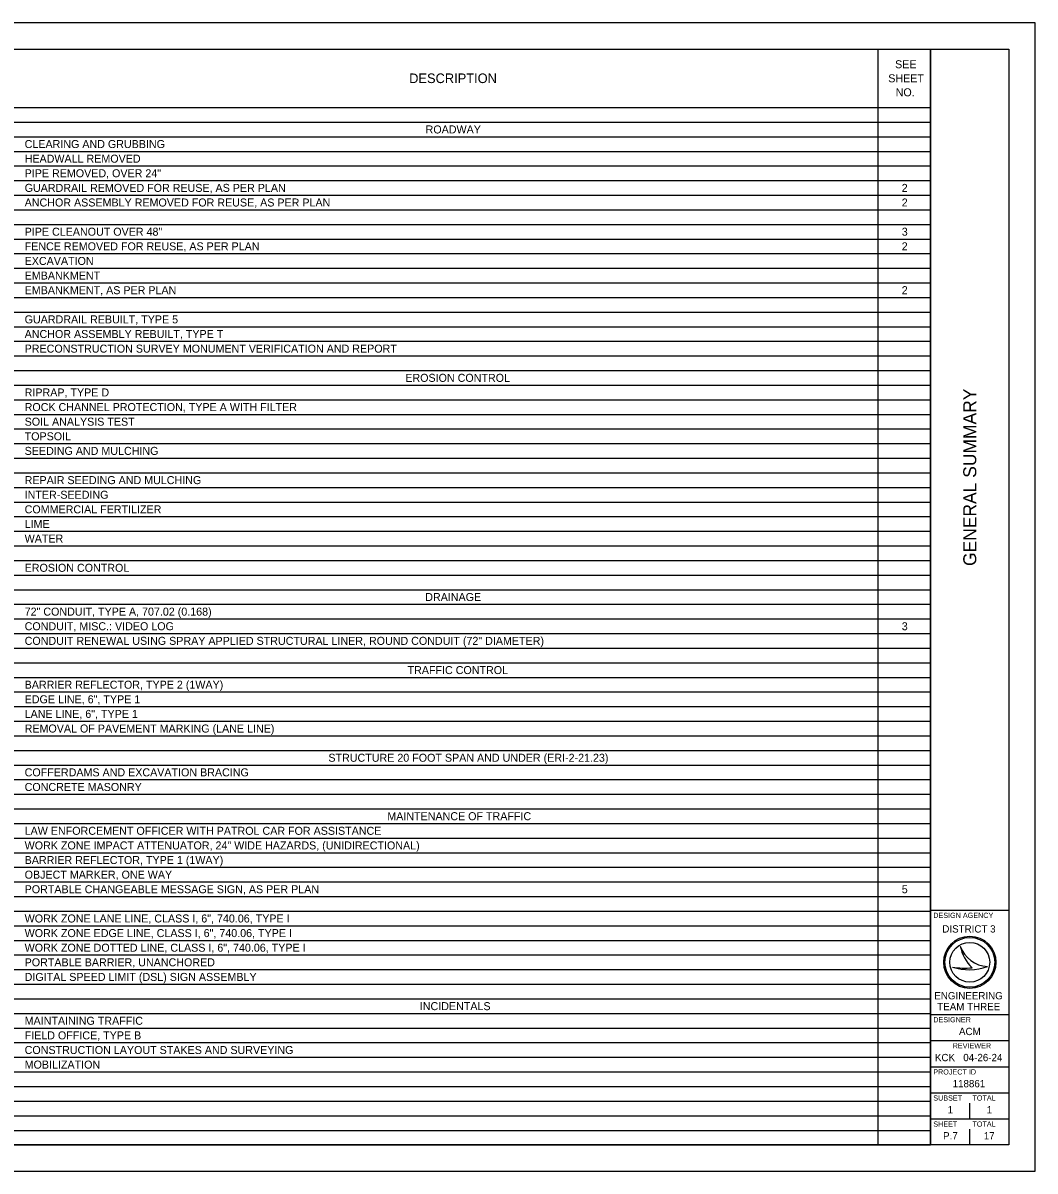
# Model space of a CAD drawing. Extents: x 0 to 34, y 0 to 22.
# Drawn here: x 14.61 to 34, y 0 to 22 of the extents above; entities that cross this region are included whole.
import ezdxf

# ---------------------------------------------------------------- set-up
doc = ezdxf.new("R2010")
doc.units = 0
for name, color, linetype in [('SH_Border', 7, 'Continuous'), ('SH_Cut_Line', 7, 'Continuous'), ('SH_Data', 7, 'Continuous'), ('SH_Text', 7, 'Continuous')]:
    doc.layers.add(name, color=color, linetype=linetype)

msp = doc.modelspace()

# ---------------------------------------------------------------- linework, layer by layer
at = {"layer": 'SH_Border'}
for p, q in [((32, 0.5), (32, 21.5)), ((32, 5), (33.5, 5)), ((32, 3), (33.5, 3)), ((32, 2.5), (33.5, 2.5)), ((32, 2), (33.5, 2)), ((32, 1.5), (33.5, 1.5)), ((32, 1), (33.5, 1))]:
    msp.add_line(p, q, dxfattribs=at)
msp.add_lwpolyline([(1.5, 21.5), (33.5, 21.5), (33.5, 0.5), (1.5, 0.5)], close=True, dxfattribs=at)
at = {"layer": 'SH_Cut_Line'}
msp.add_lwpolyline([(0, 0), (34, 0), (34, 22), (0, 22)], close=True, dxfattribs=at)
at = {"layer": 'SH_Data'}
for p, q in [((32.567, 4.31), (32.567, 4.31)), ((32.75, 4), (32.75, 4)), ((32.417, 3.91), (32.417, 3.91)), ((33.087, 3.919), (33.087, 3.919)), ((32.75, 1), (32.75, 1.3)), ((32.375, 0.675), (32.375, 0.675)), ((32.75, 0.5), (32.75, 0.8))]:
    msp.add_line(p, q, dxfattribs=at)
for radius in [0.5, 0.477, 0.477, 0.382]:
    msp.add_circle((32.75, 4), radius, dxfattribs=at)
for centre, radius, start, end in [((33.116, 4.498), 0.58, 198.9257, 198.9319), ((33.347, 4.47), 0.796, 191.6379, 191.6421), ((33.116, 4.498), 0.58, 198.9319, 267.1657), ((33.347, 4.47), 0.796, 191.6421, 226.0947), ((32.739, 4.87), 1.013, 251.4576, 290.0832), ((32.648, 5.154), 1.266, 259.4964, 259.4995), ((32.739, 4.87), 1.013, 251.4527, 251.4576), ((32.648, 5.154), 1.266, 259.4995, 276.6672)]:
    msp.add_arc(centre, radius, start, end, dxfattribs=at)
at = {"layer": 'SH_Text'}
for p, q in [((13.332, 21.5), (30.988, 21.5)), ((30.988, 21.5), (32, 21.5)), ((30.988, 21.5), (30.988, 21.22)), ((32, 21.5), (32, 21.22)), ((30.988, 21.22), (30.988, 20.94)), ((32, 21.22), (32, 20.94)), ((30.988, 20.94), (30.988, 20.66)), ((32, 20.94), (32, 20.66)), ((30.988, 20.66), (30.988, 20.38)), ((32, 20.66), (32, 20.38)), ((13.332, 20.38), (30.988, 20.38)), ((30.988, 20.38), (32, 20.38)), ((30.988, 20.38), (30.988, 20.1)), ((32, 20.38), (32, 20.1)), ((13.332, 20.1), (30.988, 20.1)), ((30.988, 20.1), (32, 20.1)), ((30.988, 20.1), (30.988, 18.7)), ((32, 20.1), (32, 18.7)), ((13.332, 19.82), (30.988, 19.82)), ((30.988, 19.82), (32, 19.82)), ((13.332, 19.54), (30.988, 19.54)), ((30.988, 19.54), (32, 19.54)), ((13.332, 19.26), (30.988, 19.26)), ((30.988, 19.26), (32, 19.26)), ((13.332, 18.98), (30.988, 18.98)), ((30.988, 18.98), (32, 18.98)), ((13.332, 18.7), (30.988, 18.7)), ((30.988, 18.7), (32, 18.7)), ((30.988, 18.7), (30.988, 18.14)), ((32, 18.7), (32, 18.14)), ((13.332, 18.42), (30.988, 18.42)), ((30.988, 18.42), (32, 18.42)), ((13.332, 18.14), (30.988, 18.14)), ((30.988, 18.14), (32, 18.14)), ((30.988, 18.14), (30.988, 17.86)), ((32, 18.14), (32, 17.86)), ((13.332, 17.86), (30.988, 17.86)), ((30.988, 17.86), (32, 17.86)), ((30.988, 17.86), (30.988, 17.58)), ((32, 17.86), (32, 17.58)), ((13.332, 17.58), (30.988, 17.58)), ((30.988, 17.58), (32, 17.58)), ((30.988, 17.58), (30.988, 17.3)), ((32, 17.58), (32, 17.3)), ((13.332, 17.3), (30.988, 17.3)), ((30.988, 17.3), (32, 17.3)), ((30.988, 17.3), (30.988, 17.02)), ((32, 17.3), (32, 17.02)), ((13.332, 17.02), (30.988, 17.02)), ((30.988, 17.02), (32, 17.02)), ((30.988, 17.02), (30.988, 16.74)), ((32, 17.02), (32, 16.74)), ((13.332, 16.74), (30.988, 16.74)), ((30.988, 16.74), (32, 16.74)), ((30.988, 16.74), (30.988, 16.18)), ((32, 16.74), (32, 16.18)), ((13.332, 16.46), (30.988, 16.46)), ((30.988, 16.46), (32, 16.46)), ((13.332, 16.18), (30.988, 16.18)), ((30.988, 16.18), (32, 16.18)), ((30.988, 16.18), (30.988, 15.9)), ((32, 16.18), (32, 15.9)), ((13.332, 15.9), (30.988, 15.9)), ((30.988, 15.9), (32, 15.9)), ((30.988, 15.9), (30.988, 15.62)), ((32, 15.9), (32, 15.62)), ((13.332, 15.62), (30.988, 15.62)), ((30.988, 15.62), (32, 15.62)), ((30.988, 15.62), (30.988, 15.34)), ((32, 15.62), (32, 15.34)), ((13.332, 15.34), (30.988, 15.34)), ((30.988, 15.34), (32, 15.34)), ((30.988, 15.34), (30.988, 14.78)), ((32, 15.34), (32, 14.78)), ((13.332, 15.06), (30.988, 15.06)), ((30.988, 15.06), (32, 15.06)), ((13.332, 14.78), (30.988, 14.78)), ((30.988, 14.78), (32, 14.78)), ((30.988, 14.78), (30.988, 14.5)), ((32, 14.78), (32, 14.5)), ((13.332, 14.5), (30.988, 14.5)), ((30.988, 14.5), (32, 14.5)), ((30.988, 14.5), (30.988, 14.22)), ((32, 14.5), (32, 14.22)), ((13.332, 14.22), (30.988, 14.22)), ((30.988, 14.22), (32, 14.22)), ((30.988, 14.22), (30.988, 13.94)), ((32, 14.22), (32, 13.94)), ((13.332, 13.94), (30.988, 13.94)), ((30.988, 13.94), (32, 13.94)), ((30.988, 13.94), (30.988, 11.7)), ((32, 13.94), (32, 11.7)), ((13.332, 13.66), (30.988, 13.66)), ((30.988, 13.66), (32, 13.66)), ((13.332, 13.38), (30.988, 13.38)), ((30.988, 13.38), (32, 13.38)), ((13.332, 13.1), (30.988, 13.1)), ((30.988, 13.1), (32, 13.1)), ((13.332, 12.82), (30.988, 12.82)), ((30.988, 12.82), (32, 12.82)), ((13.332, 12.54), (30.988, 12.54)), ((30.988, 12.54), (32, 12.54)), ((13.332, 12.26), (30.988, 12.26)), ((30.988, 12.26), (32, 12.26)), ((13.332, 11.98), (30.988, 11.98)), ((30.988, 11.98), (32, 11.98)), ((13.332, 11.7), (30.988, 11.7)), ((30.988, 11.7), (32, 11.7)), ((30.988, 11.7), (30.988, 11.42)), ((32, 11.7), (32, 11.42)), ((13.332, 11.42), (30.988, 11.42)), ((30.988, 11.42), (32, 11.42)), ((30.988, 11.42), (30.988, 10.3)), ((32, 11.42), (32, 10.3)), ((13.332, 11.14), (30.988, 11.14)), ((30.988, 11.14), (32, 11.14)), ((13.332, 10.86), (30.988, 10.86)), ((30.988, 10.86), (32, 10.86)), ((13.332, 10.58), (30.988, 10.58)), ((30.988, 10.58), (32, 10.58)), ((13.332, 10.3), (30.988, 10.3)), ((30.988, 10.3), (32, 10.3)), ((30.988, 10.3), (30.988, 10.02)), ((32, 10.3), (32, 10.02)), ((13.332, 10.02), (30.988, 10.02)), ((30.988, 10.02), (32, 10.02)), ((30.988, 10.02), (30.988, 9.74)), ((32, 10.02), (32, 9.74)), ((13.332, 9.74), (30.988, 9.74)), ((30.988, 9.74), (32, 9.74)), ((30.988, 9.74), (30.988, 8.9)), ((32, 9.74), (32, 8.9)), ((13.332, 9.46), (30.988, 9.46)), ((30.988, 9.46), (32, 9.46)), ((13.332, 9.18), (30.988, 9.18)), ((30.988, 9.18), (32, 9.18)), ((13.332, 8.9), (30.988, 8.9)), ((30.988, 8.9), (32, 8.9)), ((30.988, 8.9), (30.988, 8.34)), ((32, 8.9), (32, 8.34)), ((13.332, 8.62), (30.988, 8.62)), ((30.988, 8.62), (32, 8.62)), ((13.332, 8.34), (30.988, 8.34)), ((30.988, 8.34), (32, 8.34)), ((30.988, 8.34), (30.988, 7.5)), ((32, 8.34), (32, 7.5)), ((13.332, 8.06), (30.988, 8.06)), ((30.988, 8.06), (32, 8.06)), ((13.332, 7.78), (30.988, 7.78)), ((30.988, 7.78), (32, 7.78)), ((13.332, 7.5), (30.988, 7.5)), ((30.988, 7.5), (32, 7.5)), ((30.988, 7.5), (30.988, 6.94)), ((32, 7.5), (32, 6.94)), ((13.332, 7.22), (30.988, 7.22)), ((30.988, 7.22), (32, 7.22)), ((13.332, 6.94), (30.988, 6.94)), ((30.988, 6.94), (32, 6.94)), ((30.988, 6.94), (30.988, 6.1)), ((32, 6.94), (32, 6.1)), ((13.332, 6.66), (30.988, 6.66)), ((30.988, 6.66), (32, 6.66)), ((13.332, 6.38), (30.988, 6.38)), ((30.988, 6.38), (32, 6.38)), ((13.332, 6.1), (30.988, 6.1)), ((30.988, 6.1), (32, 6.1)), ((30.988, 6.1), (30.988, 4.98)), ((32, 6.1), (32, 4.98)), ((13.332, 5.82), (30.988, 5.82)), ((30.988, 5.82), (32, 5.82)), ((13.332, 5.54), (30.988, 5.54)), ((30.988, 5.54), (32, 5.54)), ((13.332, 5.26), (30.988, 5.26)), ((30.988, 5.26), (32, 5.26)), ((13.332, 4.98), (30.988, 4.98)), ((30.988, 4.98), (32, 4.98)), ((30.988, 4.98), (30.988, 4.7)), ((32, 4.98), (32, 4.7)), ((13.332, 4.7), (30.988, 4.7)), ((30.988, 4.7), (32, 4.7)), ((30.988, 4.7), (30.988, 3.58)), ((32, 4.7), (32, 3.58)), ((13.332, 4.42), (30.988, 4.42)), ((30.988, 4.42), (32, 4.42)), ((13.332, 4.14), (30.988, 4.14)), ((30.988, 4.14), (32, 4.14)), ((13.332, 3.86), (30.988, 3.86)), ((30.988, 3.86), (32, 3.86)), ((13.332, 3.58), (30.988, 3.58)), ((30.988, 3.58), (32, 3.58)), ((30.988, 3.58), (30.988, 3.3)), ((32, 3.58), (32, 3.3)), ((13.332, 3.3), (30.988, 3.3)), ((30.988, 3.3), (32, 3.3)), ((30.988, 3.3), (30.988, 2.18)), ((32, 3.3), (32, 2.18)), ((13.332, 3.02), (30.988, 3.02)), ((30.988, 3.02), (32, 3.02)), ((13.332, 2.74), (30.988, 2.74)), ((30.988, 2.74), (32, 2.74)), ((13.332, 2.46), (30.988, 2.46)), ((30.988, 2.46), (32, 2.46)), ((13.332, 2.18), (30.988, 2.18)), ((30.988, 2.18), (32, 2.18)), ((30.988, 2.18), (30.988, 1.9)), ((32, 2.18), (32, 1.9)), ((13.332, 1.9), (30.988, 1.9)), ((30.988, 1.9), (32, 1.9)), ((30.988, 1.9), (30.988, 0.78)), ((32, 1.9), (32, 0.78)), ((13.332, 1.62), (30.988, 1.62)), ((30.988, 1.62), (32, 1.62)), ((13.332, 1.34), (30.988, 1.34)), ((30.988, 1.34), (32, 1.34)), ((13.332, 1.06), (30.988, 1.06)), ((30.988, 1.06), (32, 1.06)), ((13.332, 0.78), (30.988, 0.78)), ((30.988, 0.78), (32, 0.78)), ((30.988, 0.78), (30.988, 0.5)), ((32, 0.78), (32, 0.5)), ((13.332, 0.5), (30.988, 0.5)), ((30.988, 0.5), (32, 0.5))]:
    msp.add_line(p, q, dxfattribs=at)

# ---------------------------------------------------------------- texts
at = {"layer": 'SH_Data'}
msp.add_text('GENERAL SUMMARY', height=0.25, rotation=90, dxfattribs=at).set_placement((32.875, 11.594))
for s, height, p in [('DESIGN AGENCY', 0.1, (32.05, 4.85)), ('DISTRICT 3', 0.14, (32.224, 4.57)), ('ENGINEERING', 0.14, (32.071, 3.29)), ('TEAM THREE', 0.14, (32.127, 3.08)), ('DESIGNER', 0.1, (32.05, 2.85)), ('ACM', 0.14, (32.543, 2.605)), ('REVIEWER', 0.1, (32.422, 2.35)), ('KCK', 0.14, (32.083, 2.105)), ('04-26-24', 0.14, (32.625, 2.105)), ('PROJECT ID', 0.1, (32.05, 1.85)), ('SUBSET', 0.1, (32.05, 1.35)), ('TOTAL', 0.1, (32.8, 1.35)), ('1', 0.14, (32.325, 1.105)), ('1', 0.14, (33.075, 1.105)), ('SHEET', 0.1, (32.05, 0.85)), ('TOTAL', 0.1, (32.8, 0.85)), ('P.7', 0.14, (32.239, 0.605)), ('17', 0.14, (33.018, 0.605))]:
    msp.add_text(s, height=height, dxfattribs=at).set_placement(p)
at = {"layer": 'SH_Text'}
for s, height, p in [('SEE ', 0.1533, (31.319, 21.132)), ('DESCRIPTION', 0.184, (22.009, 20.848)), ('SHEET ', 0.1533, (31.188, 20.863)), ('NO.', 0.1533, (31.33, 20.595)), ('ROADWAY', 0.1533, (22.324, 19.883)), ('CLEARING AND GRUBBING', 0.15333, (14.642, 19.603)), ('HEADWALL REMOVED', 0.15333, (14.642, 19.323)), ('PIPE REMOVED, OVER 24"', 0.15333, (14.642, 19.043)), ('GUARDRAIL REMOVED FOR REUSE, AS PER PLAN', 0.15333, (14.642, 18.763)), ('2', 0.153, (31.446, 18.763)), ('ANCHOR ASSEMBLY REMOVED FOR REUSE, AS PER PLAN', 0.15333, (14.642, 18.483)), ('2', 0.153, (31.446, 18.483)), ('PIPE CLEANOUT OVER 48"', 0.15333, (14.642, 17.923)), ('3', 0.153, (31.447, 17.923)), ('FENCE REMOVED FOR REUSE, AS PER PLAN', 0.15333, (14.642, 17.643)), ('2', 0.153, (31.446, 17.643)), ('EXCAVATION', 0.1533, (14.642, 17.363)), ('EMBANKMENT', 0.1533, (14.642, 17.083)), ('EMBANKMENT, AS PER PLAN', 0.15333, (14.642, 16.803)), ('2', 0.153, (31.446, 16.803)), ('GUARDRAIL REBUILT, TYPE 5', 0.15333, (14.642, 16.243)), ('ANCHOR ASSEMBLY REBUILT, TYPE T', 0.15333, (14.642, 15.963)), ('PRECONSTRUCTION SURVEY MONUMENT VERIFICATION AND REPORT', 0.15333, (14.642, 15.683)), ('EROSION CONTROL', 0.15333, (21.935, 15.123)), ('RIPRAP, TYPE D', 0.15333, (14.642, 14.843)), ('ROCK CHANNEL PROTECTION, TYPE A WITH FILTER', 0.15333, (14.642, 14.563)), ('SOIL ANALYSIS TEST', 0.15333, (14.642, 14.283)), ('TOPSOIL', 0.1533, (14.642, 14.003)), ('SEEDING AND MULCHING', 0.15333, (14.642, 13.723)), ('REPAIR SEEDING AND MULCHING', 0.15333, (14.642, 13.163)), ('INTER-SEEDING', 0.15333, (14.642, 12.883)), ('COMMERCIAL FERTILIZER', 0.15333, (14.642, 12.603)), ('LIME', 0.1533, (14.642, 12.323)), ('WATER', 0.1533, (14.642, 12.043)), ('EROSION CONTROL', 0.15333, (14.642, 11.483)), ('DRAINAGE', 0.1533, (22.317, 10.923)), ('72" CONDUIT, TYPE A, 707.02 (0.168)', 0.15333, (14.642, 10.643)), ('CONDUIT, MISC.: VIDEO LOG', 0.15333, (14.642, 10.363)), ('3', 0.153, (31.447, 10.363)), ('CONDUIT RENEWAL USING SPRAY APPLIED STRUCTURAL LINER, ROUND CONDUIT (72" DIAMETER)', 0.15333, (14.642, 10.083)), ('TRAFFIC CONTROL', 0.15333, (21.978, 9.523)), ('BARRIER REFLECTOR, TYPE 2 (1WAY)', 0.15333, (14.642, 9.243)), ('EDGE LINE, 6", TYPE 1', 0.15333, (14.642, 8.963)), ('LANE LINE, 6", TYPE 1', 0.15333, (14.642, 8.683)), ('REMOVAL OF PAVEMENT MARKING (LANE LINE)', 0.15333, (14.642, 8.403)), ('STRUCTURE 20 FOOT SPAN AND UNDER (ERI-2-21.23)', 0.15333, (20.461, 7.843)), ('COFFERDAMS AND EXCAVATION BRACING', 0.15333, (14.642, 7.563)), ('CONCRETE MASONRY', 0.15333, (14.642, 7.283)), ('MAINTENANCE OF TRAFFIC', 0.15333, (21.59, 6.723)), ('LAW ENFORCEMENT OFFICER WITH PATROL CAR FOR ASSISTANCE', 0.15333, (14.642, 6.443)), ('WORK ZONE IMPACT ATTENUATOR, 24" WIDE HAZARDS, (UNIDIRECTIONAL)', 0.15333, (14.642, 6.163)), ('BARRIER REFLECTOR, TYPE 1 (1WAY)', 0.15333, (14.642, 5.883)), ('OBJECT MARKER, ONE WAY', 0.15333, (14.642, 5.603)), ('PORTABLE CHANGEABLE MESSAGE SIGN, AS PER PLAN', 0.15333, (14.642, 5.323)), ('5', 0.153, (31.447, 5.323)), ('WORK ZONE LANE LINE, CLASS I, 6", 740.06, TYPE I', 0.15333, (14.642, 4.763)), ('WORK ZONE EDGE LINE, CLASS I, 6", 740.06, TYPE I', 0.15333, (14.642, 4.483)), ('WORK ZONE DOTTED LINE, CLASS I, 6", 740.06, TYPE I', 0.15333, (14.642, 4.203)), ('PORTABLE BARRIER, UNANCHORED', 0.15333, (14.642, 3.923)), ('DIGITAL SPEED LIMIT (DSL) SIGN ASSEMBLY', 0.15333, (14.642, 3.643)), ('INCIDENTALS', 0.15333, (22.213, 3.083)), ('MAINTAINING TRAFFIC', 0.15333, (14.642, 2.803)), ('FIELD OFFICE, TYPE B', 0.15333, (14.642, 2.523)), ('CONSTRUCTION LAYOUT STAKES AND SURVEYING', 0.15333, (14.642, 2.243)), ('MOBILIZATION', 0.15333, (14.642, 1.963)), ('118861', 0.14, (32.421, 1.605))]:
    msp.add_text(s, height=height, dxfattribs=at).set_placement(p)

doc.saveas('drawing.dxf')
